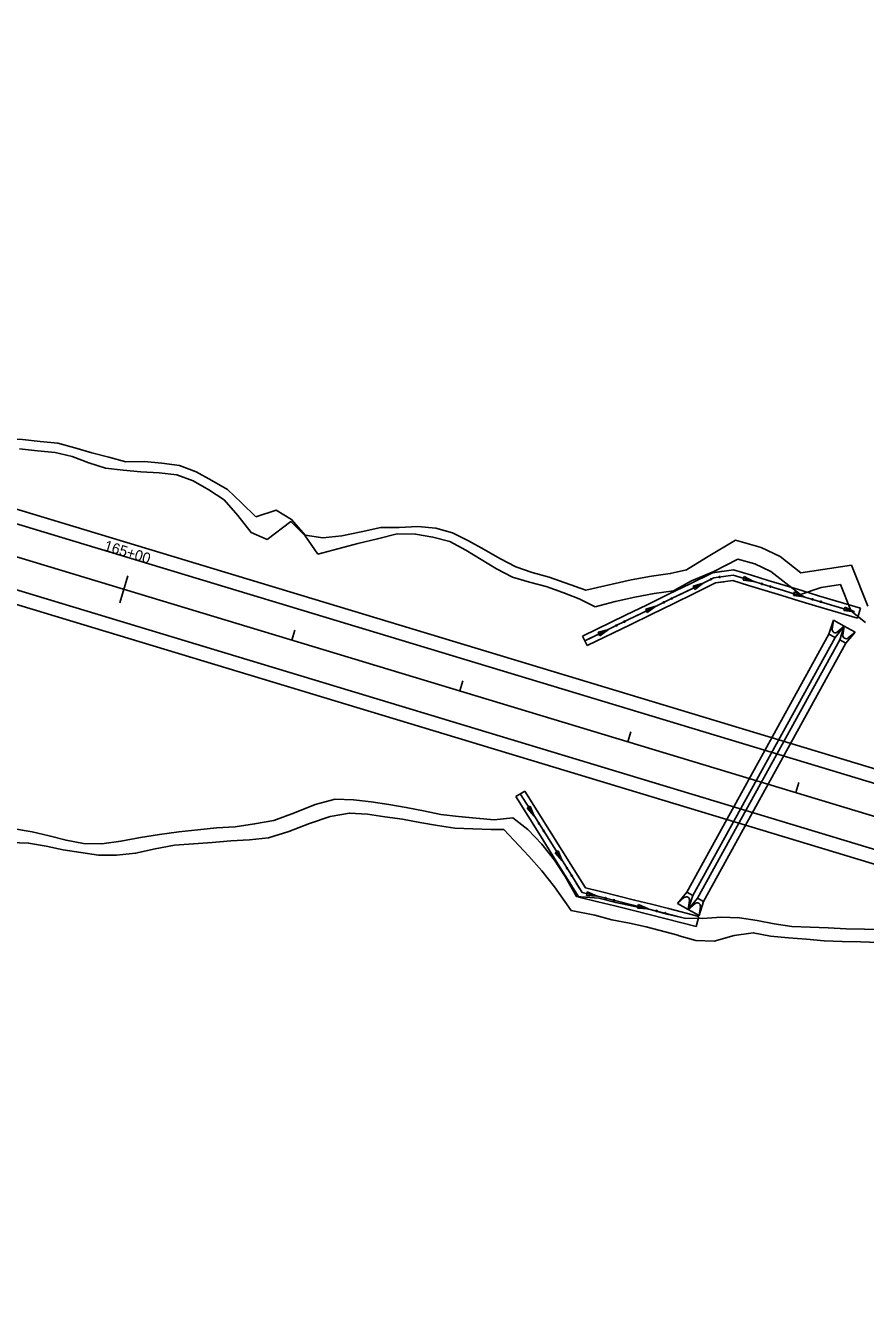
# Model space of a CAD drawing. Extents: x 979959 to 994833, y 1835619 to 1845316.
# Drawn here: x 982323 to 982802, y 1837782 to 1838507 of the extents above; entities that cross this region are included whole.
import ezdxf

# ---------------------------------------------------------------- set-up
doc = ezdxf.new("R2010")
doc.units = 0
for name, color, linetype in [('Future 5 Lane Construction Limits', 7, 'Continuous'), ('R_CONCRETE', 7, 'Continuous'), ('R_Drainage', 7, 'Continuous'), ('R_Horz Alg', 7, 'Continuous'), ('R_Horz Alg Stationing', 7, 'Continuous'), ('R_Proposed Const Limits', 7, 'Continuous'), ('R_Proposed Road', 7, 'Continuous'), ('R_Special Ditch', 7, 'Continuous')]:
    doc.layers.add(name, color=color, linetype=linetype)

msp = doc.modelspace()

# ---------------------------------------------------------------- linework, layer by layer
at = {"layer": 'Future 5 Lane Construction Limits'}
for points in [[(982301.28, 1838272.53), (982311.49, 1838271.76), (982321.73, 1838271.07), (982331.89, 1838270.1), (982342, 1838269), (982351.66, 1838266.39), (982361.27, 1838263.63), (982370.95, 1838261.1), (982380.62, 1838258.5), (982391.09, 1838258.6), (982401.27, 1838257.69), (982411.33, 1838256.41), (982420.66, 1838252.75), (982429.6, 1838247.75), (982438.53, 1838242.74), (982446.66, 1838235.07), (982454.71, 1838227.16)], [(982454.71, 1838227.16), (982466.31, 1838230.94), (982475.14, 1838225.62), (982482.88, 1838216.66)], [(982482.88, 1838216.66), (982492.87, 1838215.13), (982503.66, 1838216.27), (982514.81, 1838218.61), (982525.97, 1838220.95), (982536.44, 1838221.03), (982547.06, 1838221.6), (982557.24, 1838220.71), (982566.86, 1838217.97), (982575.9, 1838213.34), (982584.89, 1838208.5), (982593.79, 1838203.41), (982602.8, 1838198.65), (982612.28, 1838195.43), (982621.89, 1838192.65), (982642.74, 1838185.25)], [(982642.74, 1838185.25), (982668.67, 1838191.17), (982680.2, 1838193.34), (982690.92, 1838194.77), (982700.08, 1838196.82), (982711.52, 1838203.82), (982728, 1838213.7), (982742.61, 1838209.67), (982753.57, 1838204.46), (982765.23, 1838195.19)], [(982765.23, 1838195.19), (982794.12, 1838199.62), (982803.55, 1838176.14)], [(982314.97, 1838041.52), (982325.31, 1838041.16), (982335.23, 1838039.43), (982345.01, 1838037.21), (982355.02, 1838035.75), (982365.04, 1838034.33), (982375.43, 1838034.15), (982386.24, 1838035.35), (982397.42, 1838037.77), (982408.5, 1838039.86), (982419.2, 1838040.68), (982429.9, 1838041.53), (982440.59, 1838042.33), (982451.2, 1838042.88), (982462.03, 1838044.13), (982473.54, 1838047.63), (982485.4, 1838052.32), (982497.07, 1838056.36), (982508.08, 1838058.21), (982518.33, 1838057.57), (982528.3, 1838056), (982538.38, 1838054.75), (982548.27, 1838052.94), (982558.19, 1838051.17), (982568.17, 1838049.63), (982578.47, 1838049.16), (982588.83, 1838048.84), (982596.02, 1838048.81)], [(982596.02, 1838048.81), (982610.28, 1838033.71), (982617.77, 1838025.34), (982624.94, 1838016.17), (982634.4, 1838002.66), (982647.9, 1838000.02), (982657.56, 1837997.47), (982667.66, 1837995.46), (982677.15, 1837993.45), (982695.26, 1837988.59)], [(982695.26, 1837988.59), (982695.9, 1837988.35), (982705.53, 1837985.65), (982715.82, 1837985.14), (982727.25, 1837988.4), (982738.2, 1837990.05), (982748.07, 1837988.14), (982758.2, 1837987.1), (982768.42, 1837986.35), (982778.6, 1837985.45), (982788.9, 1837984.96), (982799.3, 1837984.8), (982809.63, 1837984.4), (982819.9, 1837983.83), (982830.34, 1837983.79)]]:
    msp.add_lwpolyline(points, dxfattribs=at)
at = {"layer": 'R_CONCRETE'}
for p, q in [((982640.93, 1838159.05), (982643.56, 1838153.66)), ((982602.89, 1838067.61), (982607.97, 1838070.8))]:
    msp.add_line(p, q, dxfattribs=at)
for points in [[(982640.93, 1838159.05), (982665.43, 1838170.98), (982677.69, 1838176.95), (982689.95, 1838182.95), (982702.21, 1838188.96), (982714.91, 1838195.2), (982720.84, 1838196.03)], [(982643.56, 1838153.66), (982668.06, 1838165.58), (982680.32, 1838171.56), (982692.59, 1838177.56), (982704.85, 1838183.57), (982716.7, 1838189.39), (982721.68, 1838190.09)]]:
    msp.add_lwpolyline(points, dxfattribs=at)
at = {"layer": 'R_Drainage'}
for p, q in [((982799.35, 1838175.01), (982797.65, 1838169.26)), ((982781.27, 1838160.29), (982783.9, 1838168.17)), ((982783.14, 1838163.1), (982783.9, 1838168.17)), ((982783.9, 1838168.17), (982790.03, 1838164.79)), ((982700.26, 1838013.12), (982781.27, 1838160.29)), ((982703.76, 1838011.19), (982784.78, 1838158.36)), ((982781.27, 1838160.29), (982784.78, 1838158.36)), ((982784.78, 1838158.36), (982790.03, 1838164.79)), ((982786.15, 1838161.44), (982790.03, 1838164.79)), ((982787.41, 1838156.91), (982790.03, 1838164.79)), ((982789.27, 1838159.72), (982790.03, 1838164.79)), ((982790.03, 1838164.79), (982796.16, 1838161.42)), ((982790.91, 1838154.98), (982796.16, 1838161.42)), ((982792.28, 1838158.06), (982796.16, 1838161.42)), ((982706.39, 1838009.74), (982787.41, 1838156.91)), ((982709.89, 1838007.81), (982790.91, 1838154.98)), ((982787.41, 1838156.91), (982790.91, 1838154.98)), ((982700.26, 1838013.12), (982695, 1838006.68)), ((982700.26, 1838013.12), (982703.76, 1838011.19)), ((982698.88, 1838010.04), (982695, 1838006.68)), ((982695, 1838006.68), (982701.13, 1838003.31)), ((982703.76, 1838011.19), (982701.13, 1838003.31)), ((982706.39, 1838009.74), (982701.13, 1838003.31)), ((982701.89, 1838008.38), (982701.13, 1838003.31)), ((982705.01, 1838006.66), (982701.13, 1838003.31)), ((982706.39, 1838009.74), (982709.89, 1838007.81)), ((982709.89, 1838007.81), (982707.27, 1837999.93)), ((982701.13, 1838003.31), (982707.27, 1837999.93)), ((982707.12, 1837999.36), (982705.63, 1837993.54)), ((982708.03, 1838005), (982707.27, 1837999.93))]:
    msp.add_line(p, q, dxfattribs=at)
for points in [[(982640.93, 1838159.05), (982665.43, 1838170.98), (982677.69, 1838176.95), (982689.95, 1838182.95), (982702.21, 1838188.96), (982714.91, 1838195.2), (982726.96, 1838196.9), (982737.16, 1838193.75), (982746.71, 1838190.82), (982756.27, 1838187.91), (982765.84, 1838185.02), (982775.41, 1838182.14), (982784.99, 1838179.28), (982799.35, 1838175.01)], [(982643.56, 1838153.66), (982668.06, 1838165.58), (982680.32, 1838171.56), (982692.59, 1838177.56), (982704.85, 1838183.57), (982716.7, 1838189.39), (982726.47, 1838190.77), (982735.39, 1838188.02), (982744.96, 1838185.09), (982754.53, 1838182.17), (982764.11, 1838179.27), (982773.69, 1838176.39), (982783.27, 1838173.53), (982797.65, 1838169.26)], [(982602.89, 1838067.61), (982617, 1838045.17), (982624.05, 1838033.94), (982631.09, 1838022.69), (982638.77, 1838010.38), (982649.67, 1838007.69), (982659.38, 1838005.28), (982669.09, 1838002.85), (982678.79, 1838000.4), (982688.49, 1837997.94), (982705.63, 1837993.54)], [(982607.97, 1838070.8), (982622.08, 1838048.36), (982629.13, 1838037.12), (982636.18, 1838025.87), (982642.57, 1838015.62), (982651.11, 1838013.52), (982660.83, 1838011.1), (982670.55, 1838008.67), (982680.26, 1838006.22), (982689.97, 1838003.75), (982707.12, 1837999.36)]]:
    msp.add_lwpolyline(points, dxfattribs=at)
for centre, start, end in [((982784.95, 1838162.83), 171.48659, 310.84943), ((982791.09, 1838159.45), 171.48659, 310.84943), ((982700.08, 1838008.65), 351.48642, 130.84926), ((982706.21, 1838005.27), 351.48642, 130.84926)]:
    msp.add_arc(centre, 1.83, start, end, dxfattribs=at)
at = {"layer": 'R_Horz Alg'}
msp.add_line((981399.33, 1838482.26), (983633.31, 1837806.41), dxfattribs=at)
at = {"layer": 'R_Horz Alg Stationing'}
for points in [[(982381.81, 1838193.38), (982377.18, 1838178.07)], [(982476.95, 1838162.51), (982475.21, 1838156.77)], [(982572.66, 1838133.56), (982570.93, 1838127.81)], [(982668.38, 1838104.6), (982666.64, 1838098.86)], [(982764.1, 1838075.64), (982762.36, 1838069.9)]]:
    msp.add_lwpolyline(points, dxfattribs=at)
at = {"layer": 'R_Proposed Const Limits'}
for p, q in [((982756.67, 1838189.22), (982765.16, 1838182.75)), ((982776.84, 1838186.85), (982765.16, 1838182.75)), ((982659.49, 1838178.82), (982648.14, 1838175.83)), ((982609.73, 1838048.86), (982601.27, 1838055.43)), ((982689.15, 1838000.58), (982698.92, 1837998.36))]:
    msp.add_line(p, q, dxfattribs=at)
for points in [[(982320.17, 1838265.92), (982330.28, 1838264.78), (982340.39, 1838263.66), (982350.14, 1838261.38), (982359.53, 1838257.89), (982369.05, 1838254.79), (982379.14, 1838253.64), (982389.31, 1838252.72), (982399.62, 1838252.24), (982409.67, 1838250.92), (982419.11, 1838247.61), (982428, 1838242.45), (982436.7, 1838236.69), (982444.5, 1838227.91), (982452.01, 1838218.23), (982461.24, 1838214.18)], [(982461.24, 1838214.18), (982474.75, 1838224.33), (982482.77, 1838216.29), (982490.07, 1838205.89)], [(982490.07, 1838205.89), (982501.41, 1838208.85), (982512.78, 1838211.89), (982524.05, 1838214.61), (982535.32, 1838217.31), (982545.75, 1838217.28), (982555.67, 1838215.53), (982565.35, 1838213), (982574.34, 1838208.17), (982583.16, 1838202.78), (982591.97, 1838197.36), (982601, 1838192.68), (982610.59, 1838189.86), (982620.27, 1838187.31), (982629.72, 1838184), (982639.05, 1838180.32), (982648.14, 1838175.83)], [(982659.49, 1838178.82), (982670.71, 1838181.37), (982681.79, 1838183.47), (982692.68, 1838184.91), (982703.06, 1838190.57), (982715.77, 1838195.97), (982729.47, 1838202.92), (982739.11, 1838200.26), (982748.24, 1838195.92), (982756.67, 1838189.22)], [(982776.84, 1838186.85), (982787.8, 1838188.53), (982793.76, 1838173.69)], [(982793.72, 1838173.56), (982802.15, 1838166.88)], [(982317.31, 1838049.24), (982327.26, 1838047.6), (982337, 1838045.25), (982346.67, 1838042.7), (982356.59, 1838040.96), (982366.96, 1838040.69), (982377.86, 1838042.19), (982388.94, 1838044.29), (982399.92, 1838046.04), (982410.82, 1838047.52), (982421.63, 1838048.74), (982432.39, 1838049.76), (982443.03, 1838050.39), (982453.99, 1838052.09), (982465.03, 1838054.04), (982476.81, 1838058.44), (982488.65, 1838063.06), (982500.02, 1838066.09), (982510.36, 1838065.74), (982520.48, 1838064.66), (982530.46, 1838063.13), (982540.41, 1838061.47), (982550.27, 1838059.54), (982560.1, 1838057.5), (982570.19, 1838056.3), (982580.35, 1838055.36), (982590.48, 1838054.32), (982601.27, 1838055.43)], [(982605.43, 1838069.21), (982612.49, 1838057.99), (982619.54, 1838046.77), (982626.59, 1838035.53), (982633.63, 1838024.28), (982640.67, 1838013), (982650.39, 1838010.61), (982660.11, 1838008.19), (982669.82, 1838005.76), (982679.53, 1838003.31), (982689.23, 1838000.85), (982698.92, 1837998.36)], [(982609.73, 1838048.86), (982617.64, 1838040.48), (982624.9, 1838031.48), (982630.92, 1838022.12), (982637.42, 1838010.75), (982650.14, 1838009.77), (982659.81, 1838007.21), (982669.67, 1838005.26), (982679.49, 1838003.18), (982689.15, 1838000.58)], [(982621.4, 1838043.81), (982621.42, 1838043.78)], [(982637.33, 1838018.35), (982637.35, 1838018.31)], [(982663.71, 1838007.29), (982663.75, 1838007.28)], [(982692.83, 1837999.92), (982692.87, 1837999.91)], [(982698.92, 1837998.36), (982709.31, 1837998.16), (982719.97, 1837998.84), (982730.33, 1837998.57), (982740.31, 1837997.04), (982750.16, 1837995.05), (982760.14, 1837993.49), (982770.51, 1837993.23), (982780.81, 1837992.77), (982791.11, 1837992.26), (982801.52, 1837992.15), (982811.9, 1837991.92), (982822.12, 1837991.15), (982832.36, 1837990.48), (982842.57, 1837989.7), (982852.81, 1837989.01), (982862.93, 1837987.92), (982872.77, 1837985.91)]]:
    msp.add_lwpolyline(points, dxfattribs=at)
at = {"layer": 'R_Proposed Road'}
for p, q in [((981406.86, 1838507.14), (983640.84, 1837831.3)), ((981404.54, 1838499.48), (983638.52, 1837823.64)), ((981394.12, 1838465.03), (983628.1, 1837789.18)), ((981391.8, 1838457.37), (983625.78, 1837781.53))]:
    msp.add_line(p, q, dxfattribs=at)
at = {"layer": 'R_Special Ditch'}
for p, q in [((982709.71, 1838189.3), (982703.86, 1838187.6)), ((982703.86, 1838187.6), (982704.79, 1838185.7)), ((982704.79, 1838185.7), (982709.71, 1838189.3)), ((982732.98, 1838193.01), (982732.36, 1838190.99)), ((982732.36, 1838190.99), (982738.4, 1838190.23)), ((982738.4, 1838190.23), (982732.98, 1838193.01)), ((982761.7, 1838184.24), (982761.09, 1838182.21)), ((982761.09, 1838182.21), (982767.14, 1838181.49)), ((982767.14, 1838181.49), (982761.7, 1838184.24)), ((982682.74, 1838176.08), (982676.88, 1838174.4)), ((982676.88, 1838174.4), (982677.81, 1838172.49)), ((982677.81, 1838172.49), (982682.74, 1838176.08)), ((982790.47, 1838175.62), (982789.87, 1838173.6)), ((982789.87, 1838173.6), (982795.92, 1838172.9)), ((982795.92, 1838172.9), (982790.47, 1838175.62)), ((982655.74, 1838162.92), (982649.88, 1838161.25)), ((982649.88, 1838161.25), (982650.8, 1838159.34)), ((982650.8, 1838159.34), (982655.74, 1838162.92)), ((982611.12, 1838062.15), (982609.33, 1838061.02)), ((982609.33, 1838061.02), (982613.42, 1838056.51)), ((982613.42, 1838056.51), (982611.12, 1838062.15)), ((982627.1, 1838036.71), (982625.3, 1838035.59)), ((982625.3, 1838035.59), (982629.38, 1838031.06)), ((982629.38, 1838031.06), (982627.1, 1838036.71)), ((982643.58, 1838013.37), (982643.08, 1838011.32)), ((982649.16, 1838010.91), (982643.58, 1838013.37)), ((982643.08, 1838011.32), (982649.16, 1838010.91)), ((982672.74, 1838006.12), (982672.22, 1838004.06)), ((982678.3, 1838003.62), (982672.74, 1838006.12)), ((982672.22, 1838004.06), (982678.3, 1838003.62))]:
    msp.add_line(p, q, dxfattribs=at)
for points in [[(982642.25, 1838156.36), (982666.75, 1838168.28), (982679, 1838174.26), (982691.27, 1838180.25), (982703.53, 1838186.26), (982715.8, 1838192.29), (982726.72, 1838193.83), (982736.27, 1838190.89), (982745.83, 1838187.95), (982755.4, 1838185.04), (982764.97, 1838182.14), (982774.55, 1838179.26), (982784.13, 1838176.4), (982793.72, 1838173.56)], [(982696.24, 1838182.69), (982703.53, 1838186.26), (982709.71, 1838189.3)], [(982723.93, 1838193.44), (982723.97, 1838193.45)], [(982723.97, 1838193.45), (982726.72, 1838193.83), (982736.27, 1838190.89), (982738.4, 1838190.23)], [(982696.21, 1838182.67), (982696.24, 1838182.69)], [(982752.75, 1838185.85), (982752.78, 1838185.84)], [(982752.78, 1838185.84), (982755.4, 1838185.04), (982764.97, 1838182.14), (982767.14, 1838181.49)], [(982669.26, 1838169.5), (982679, 1838174.26), (982682.74, 1838176.08)], [(982781.51, 1838177.19), (982781.54, 1838177.17)], [(982781.54, 1838177.17), (982784.13, 1838176.4), (982793.72, 1838173.56)], [(982669.22, 1838169.48), (982669.26, 1838169.5)], [(982642.25, 1838156.36), (982655.74, 1838162.92)], [(982605.43, 1838069.21), (982612.49, 1838057.99), (982613.42, 1838056.51)], [(982621.42, 1838043.77), (982626.59, 1838035.53), (982629.38, 1838031.06)], [(982637.35, 1838018.31), (982640.67, 1838013), (982649.16, 1838010.91)], [(982663.75, 1838007.28), (982669.82, 1838005.76), (982678.3, 1838003.62)], [(982692.87, 1837999.91), (982698.92, 1837998.36)]]:
    msp.add_lwpolyline(points, dxfattribs=at)
for centre in [(982714.19, 1838191.54), (982718.99, 1838192.78), (982743.2, 1838188.8), (982747.99, 1838187.34), (982691.72, 1838180.51), (982771.94, 1838180.09), (982687.22, 1838178.31), (982776.74, 1838178.65), (982660.22, 1838165.14), (982664.73, 1838167.33), (982616.11, 1838052.29), (982618.78, 1838048.05), (982632.07, 1838026.84), (982634.72, 1838022.59), (982654.02, 1838009.74), (982658.89, 1838008.53), (982683.16, 1838002.43), (982688.01, 1838001.19)]:
    msp.add_circle(centre, 0.375, dxfattribs=at)

# ---------------------------------------------------------------- texts
at = {"layer": 'R_Horz Alg Stationing'}
msp.add_text('165+00', height=6, rotation=343.16792, dxfattribs=at).set_placement((982367.82, 1838208.07))

doc.saveas('drawing.dxf')
